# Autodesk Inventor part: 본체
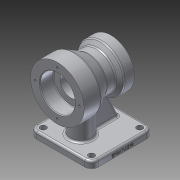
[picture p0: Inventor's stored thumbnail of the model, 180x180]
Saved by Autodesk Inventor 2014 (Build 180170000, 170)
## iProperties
Created: 2019-01
Part Number: 본체
Material: 알루미늄 6061
Document SubType Name: Modeling
Designer: 거성
Density: 2.71 g/cm^3
Appearance: 알루미늄 - 평지
Mass: 902.15 g
Surface Area: 600.961 cm^2
Volume: 332.897 cm^3
Author: 거성
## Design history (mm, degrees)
sketch "스케치3"
  geometry: L1 (0, 40)-(0, -40); L2 (26, 40)-(40, 40); L3 (40, 40)-(40, 15); L4 (40, 15)-(28, -5.785); L5 (28, -5.785)-(28, -19.126); L6 (35, -40)-(20, -40); L7 (20, -40)-(20, -23); L8 (20, -23)-(16, -23); L9 (16, -23)-(16, 20); L10 (16, 20)-(26, 20); L11 (26, 20)-(26, 40); L12 (28, -19.126)-(35, -25); L13 (35, -25)-(35, -40); 2 further points
  constraints: 26 end point, 6 parallel, 4 perpendicular, 2 horizontal alignment, 1 coincident, 1 midpoint, 1 vertical
  dimensions: "d0" = 80 distance of L1.start L1.end; "d1" = 80 diameter of L3 L1; "d2" = 52 diameter of L11 L1; "d8" = 25 distance of L2.end L3.end; "d10" = 20 distance of L10.end L2.start; "d14" = 30 deg angle of L4 L5; "d16" = 50 deg angle of L12 L5; "d17" = 70 diameter of L13 L1; "d18" = 40 diameter of L7 L1; "d19" = 32 diameter of L9 L1; "d20" = 15 distance of L12.end L6.start; "d21" = 17 distance of L6.end L7.end; "d22" = 56 diameter of L5 L1
revolve "회전1" sketch "스케치3" stored, may be unused: angle "d23" = 90 deg
node "작업 평면1"
sketch "스케치4"
  geometry: L1 (-40, 40)-(40, 40) reference; L2 (0, 40)-(0, 35); L3 (46, 35)-(-46, 35); L4 (-46, 35)-(-46, -57); L5 (-46, -57)-(46, -57); L6 (46, -57)-(46, 35); L7 (46, 35)-(-46, -57); L8 (-46, 35)-(46, -57); 2 further points
  constraints: 14 end point, 4 midpoint, 2 parallel, 2 perpendicular, 1 horizontal
  dimensions: "d25" = 5 distance of L2.end L2.start; "d26" = 92 distance of L5.end L4.end; "d27" = 92 distance of L4.end L3.end
extrude "돌출1" join sketch "스케치4" distance "d28" = 10; taper "d29" = 0 deg
sketch "스케치5"
  geometry: L1 (-46, -35)-(46, -35) reference; L2 (46, -35)-(46, 57) reference; L3 (-46, 57)-(-46, -35) reference; L4 (-46, -5)-(46, -5); L5 (0, -5)-(0, 57); L6 (-5, 10.199)-(-5, 47); L7 (5, 10.199)-(5, 47); L8 (-5, 47)-(5, 47); L9 (46, 57)-(-46, 57) reference; A1 r 16 centre (0, -5) between (5, 10.199) and (-5, 10.199); 1 further point
  constraints: 10 end point, 2 parallel, 2 perpendicular, 2 point on circle, 2 point on line, 1 centre point, 1 midpoint
  dimensions: "d30" = 30 distance between parallel lines of L1 L4; "d31" = 32 diameter of A1; "d32" = 5 distance between parallel lines of L6 L5; "d33" = 10 distance between parallel lines of L7 L6; "d35" = 10 distance between parallel lines of L8 L9; "d36" = 62 distance of L5.start L5.end
extrude "돌출2" join sketch "스케치5" stored distance "d37" = 10; taper "d38" = 0 deg
node "작업 평면2"
sketch "스케치7"
  geometry: L1 (-70, -57)-(-70, 35) reference; L2 (-28, -19.126)-(-35, -25) reference; L3 (-70, -11)-(-28, -11) reference; L4 (-80, -57)-(-70, -57) reference; L5 (-70, -47)-(-20, -23.685); L6 (-70, -11)-(-70, -47); L7 (-20, -40)-(-20, -23) reference; L8 (-20, -23.685)-(-20, -9.445); L9 (-20, -9.445)-(-70, -9.445); L10 (-70, -11)-(-70, -9.445); 1 further point
  constraints: 10 end point, 3 point on line, 2 collinear, 2 perpendicular
  dimensions: "d46" = 25 deg angle of L5 L4; "d47" = 10 distance from line of L5.start L4; "d58" = 14.23927 distance of L5.end L8.end
extrude "돌출3" join sketch "스케치7" stored distance "d48" = 10; taper "d49" = 0 deg
sketch "스케치10"
  geometry: A1 r 27.5 centre (0, 0) between (0, 27.5) and (27.5, 0); 2 further points
  constraints: 4 point on circle, 1 centre point
  dimensions: "d59" = 55 diameter of A1
hole "구멍2" sketch "스케치10" at (0, -27.5), (27.5, 0), (0, 27.5), (-27.5, 0) diameter "d60" = 3.242; stored, may be unused: countersink angle "d64" = 90 deg, drill point angle "d66" = 118 deg; dims "d61" = 9, "d62" = 4, "d63" = 2, "d65" = 11
sketch "스케치11"
  geometry: C1 r 26 at (0, 0) reference; A1 r 33 centre (0, 0) between (0, 33) and (33, 0); 2 further points
  constraints: 4 point on circle, 1 centre point, 1 coincident
  dimensions: "d67" = 66 diameter of A1
hole "구멍3" sketch "스케치11" at (0, 33), (33, 0), (0, -33), (-33, 0) diameter "d68" = 3.242; stored, may be unused: countersink angle "d72" = 90 deg, drill point angle "d74" = 118 deg; dims "d69" = 9, "d70" = 4, "d71" = 2, "d73" = 11
sketch "스케치13"
  geometry: L1 (0, 0)-(92, 0) reference; L2 (0, 0)-(0, 10) reference; 2 further points
  constraints: 1 other
  dimensions: "d75" = 46 distance from line of point (46, 4) L2; "d76" = 4 distance from line of L1 point (46, 4)
feature "엠보싱1" sketch "스케치13" dims "d0" = 80, "d1" = 80, "d2" = 52, "d8" = 25, "d10" = 20, "d14" = 30 deg, "d16" = 50 deg, "d17" = 70, "d18" = 40, "d19" = 32, "d20" = 15, "d21" = 17, "d22" = 56, "d25" = 5, "d26" = 92, "d27" = 92, "d77" = 0.5, "d78" = 0
fillet "모깎기1" dims "d79" = 10
sketch "스케치14"
  geometry: C1 r 4.5 at (-36, 47); C2 r 4.5 at (36, 47); C3 r 4.5 at (36, -25); C4 r 4.5 at (-36, -25); A1 r 10 centre (36, 47) between (46, 47) and (36, 57) reference; A2 r 10 centre (-36, 47) between (-36, 57) and (-46, 47) reference; A3 r 10 centre (-36, -25) between (-46, -25) and (-36, -35) reference; A4 r 10 centre (36, -25) between (36, -35) and (46, -25) reference; 1 further point
  constraints: 4 centre point, 4 coincident
  dimensions: "d80" = 9 diameter of C1; "d81" = 9 diameter of C2; "d82" = 9 diameter of C3; "d83" = 9 diameter of C4
extrude "돌출4" cut sketch "스케치14" stored distance "d84" = 10; taper "d85" = 0 deg
fillet "모깎기2" dims "d86" = 1
fillet "모깎기3" dims "d87" = 0.6
fillet "모깎기4" dims "d88" = 3
fillet "모깎기5" dims "d89" = 3
fillet "모깎기6" dims "d90" = 3
fillet "모깎기7" dims "d91" = 3
fillet "모깎기8" dims "d92" = 3
chamfer "모따기1" distance "d93" = 1; stored, may be unused: second distance "d94" = 2, angle "d95" = 45 deg
chamfer "모따기2" distance "d96" = 1; stored, may be unused: second distance "d97" = 2, angle "d98" = 45 deg
node "솔리드1"
other parameters: "d43" = 0
